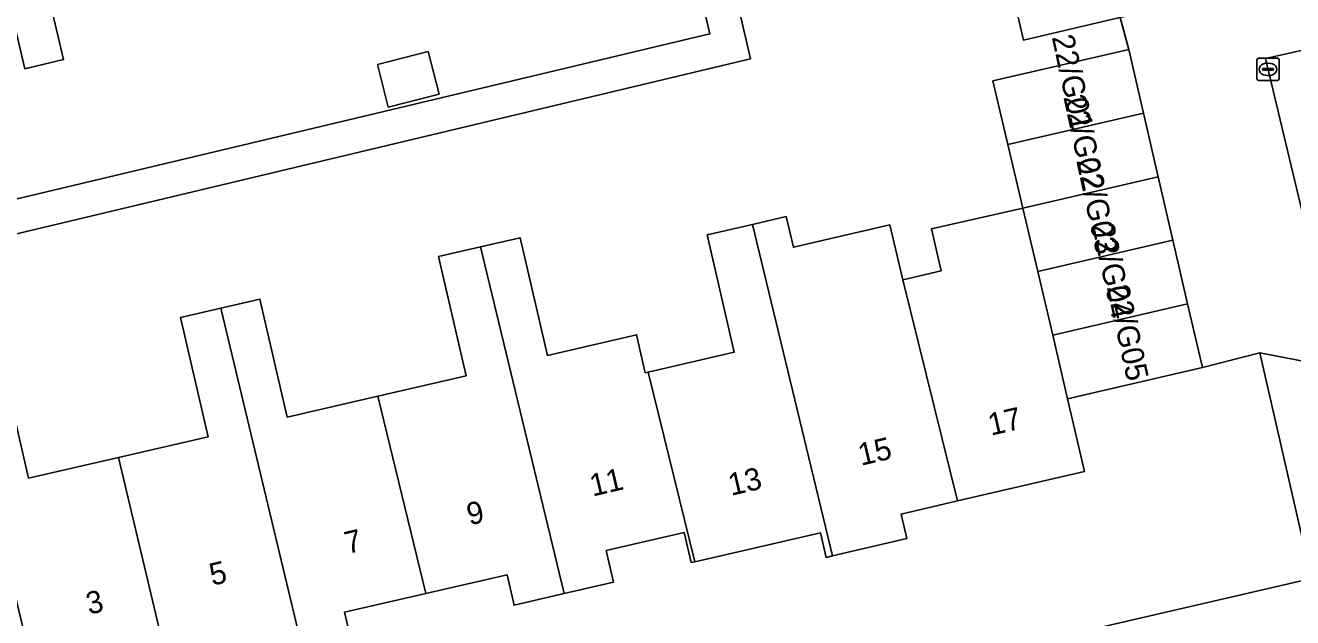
# Model space of a CAD drawing. Extents: x 158031 to 159244, y 380104 to 381214.
# Drawn here: x 158624 to 158681, y 380797.4 to 380824 of the extents above; entities that cross this region are included whole.
import ezdxf

# ---------------------------------------------------------------- set-up
doc = ezdxf.new("R2010")
doc.units = 0
for name, color, linetype in [('IMGEO_Erf', 7, 'Continuous'), ('IMGEO_Kolk', 7, 'Continuous'), ('IMGEO_Pand', 7, 'Continuous'), ('IMGEO_Pand_nummerreeks', 7, 'Continuous'), ('IMGEO_Rijbaan_lokaal_open', 7, 'Continuous'), ('IMGEO_Voetpad_open', 7, 'Continuous')]:
    doc.layers.add(name, color=color, linetype=linetype)

msp = doc.modelspace()

# ---------------------------------------------------------------- linework, layer by layer
at = {"layer": 'IMGEO_Erf'}
for points in [[(158619.439, 380815.23), (158654.76, 380823.659), (158652.218, 380834.399), (158647.944, 380833.388), (158649.195, 380828.097), (158647.343, 380827.659), (158645.589, 380827.244), (158644.337, 380832.534), (158640.266, 380831.571), (158636.181, 380830.604), (158637.434, 380825.306), (158635.642, 380824.882), (158633.881, 380824.465), (158632.636, 380829.729), (158628.571, 380828.767), (158624.437, 380827.789), (158625.69, 380822.495), (158623.945, 380822.082)], [(158672.677, 380824.263), (158668.856, 380823.374), (158667.866, 380827.629)], [(158655.594, 380826.799), (158656.575, 380822.533), (158619.79, 380813.755)], [(158623.374, 380806.866), (158624.117, 380803.653), (158628.154, 380804.587), (158632.194, 380805.522), (158630.951, 380810.889), (158632.757, 380811.307), (158634.516, 380811.714), (158635.746, 380806.4), (158639.827, 380807.345), (158643.791, 380808.262), (158642.55, 380813.627), (158644.438, 380814.064), (158646.221, 380814.477), (158647.446, 380809.184), (158651.456, 380810.113), (158651.852, 380808.4), (158651.976, 380808.429), (158655.853, 380809.326), (158654.632, 380814.602), (158656.664, 380815.072), (158658.189, 380815.425), (158658.508, 380814.046), (158662.847, 380815.05), (158663.432, 380812.582), (158665.154, 380812.981), (158664.714, 380814.879), (158668.834, 380815.814), (158668.157, 380818.673), (158667.48, 380821.533), (158673.591, 380822.947), (158673.21, 380824.387)], [(158649.671, 380791.7), (158681.807, 380799.138), (158679.48, 380809.301), (158676.904, 380808.635), (158670.839, 380807.231), (158671.598, 380803.951), (158665.887, 380802.629), (158663.356, 380802.043), (158663.614, 380800.934), (158660.269, 380800.159), (158659.981, 380800.092), (158659.723, 380801.202), (158654.075, 380799.895), (158653.912, 380799.857), (158653.6, 380801.204), (158650.096, 380800.393), (158650.424, 380798.976), (158648.201, 380798.461), (158645.948, 380797.94), (158645.632, 380799.309), (158641.979, 380798.463), (158638.327, 380797.618), (158638.653, 380796.208)]]:
    msp.add_lwpolyline(points, dxfattribs=at)
msp.add_lwpolyline([(158642.088, 380822.856), (158642.577, 380820.94), (158640.293, 380820.357), (158639.804, 380822.273)], close=True, dxfattribs=at)
at = {"layer": 'IMGEO_Kolk'}
for p, q in [((158679.352, 380821.63), (158679.352, 380822.482)), ((158679.427, 380822.556), (158680.279, 380822.556)), ((158680.353, 380822.482), (158680.353, 380821.63)), ((158679.611, 380822.05), (158679.611, 380822.062)), ((158680.049, 380822.013), (158679.651, 380822.013)), ((158679.654, 380822.099), (158680.052, 380822.099)), ((158679.84, 380822.336), (158679.865, 380822.336)), ((158680.095, 380822.062), (158680.095, 380822.05)), ((158680.279, 380821.556), (158679.427, 380821.556)), ((158679.863, 380821.776), (158679.838, 380821.776))]:
    msp.add_line(p, q, dxfattribs=at)
for points in [[(158679.352, 380821.63), (158679.352, 380822.482)], [(158679.427, 380822.556), (158680.279, 380822.556)], [(158680.353, 380822.482), (158680.353, 380821.63)], [(158680.279, 380821.556), (158679.427, 380821.556)]]:
    msp.add_lwpolyline(points, dxfattribs=at)
for centre, radius, start, end in [((158679.429, 380822.48), 0.0765, 91.552, 178.448), ((158679.429, 380822.48), 0.0765, 91.552, 178.448), ((158680.277, 380822.48), 0.0765, 1.552, 88.448), ((158680.277, 380822.48), 0.0765, 1.552, 88.448), ((158679.651, 380822.059), 0.0403, 85.8775, 175.7526), ((158679.648, 380822.049), 0.0366, 178.938, 274.7102), ((158680.052, 380822.056), 0.043, 264.8664, 352.4533), ((158680.056, 380822.061), 0.0386, 1.7309, 96.639), ((158679.429, 380821.632), 0.0765, 181.552, 268.448), ((158679.429, 380821.632), 0.0765, 181.552, 268.448), ((158680.277, 380821.632), 0.0765, 271.552, 358.448), ((158680.277, 380821.632), 0.0765, 271.552, 358.448)]:
    msp.add_arc(centre, radius, start, end, dxfattribs=at)
for centre, major_axis, ratio, start_param, end_param in [((158679.839, 380822.056), (-0.387, 0.002), 0.722429, 4.712389, 7.853982), ((158679.864, 380822.056), (-0.39, 0.002), 0.717154, 1.570796, 4.712389)]:
    msp.add_ellipse(centre, major_axis=major_axis, ratio=ratio, start_param=start_param, end_param=end_param, dxfattribs=at)
at = {"layer": 'IMGEO_Pand'}
for points in [[(158623.945, 380822.082), (158625.69, 380822.495), (158624.437, 380827.789), (158628.571, 380828.767), (158626.506, 380837.484), (158620.666, 380836.102)], [(158662.106, 380828.273), (158662.544, 380826.391), (158667.866, 380827.629), (158668.856, 380823.374), (158672.677, 380824.263), (158673.21, 380824.387), (158677.546, 380825.396), (158676.138, 380831.449)], [(158642.088, 380822.856), (158639.804, 380822.273), (158640.293, 380820.357), (158642.577, 380820.94)], [(158668.157, 380818.673), (158674.254, 380820.085), (158673.591, 380822.947), (158667.48, 380821.533)], [(158674.916, 380817.222), (158674.254, 380820.085), (158668.157, 380818.673), (158668.834, 380815.814)], [(158669.505, 380812.954), (158675.579, 380814.36), (158674.916, 380817.222), (158668.834, 380815.814)], [(158669.505, 380812.954), (158668.834, 380815.814), (158664.714, 380814.879), (158665.154, 380812.981), (158663.432, 380812.582), (158665.887, 380802.629), (158671.598, 380803.951), (158670.839, 380807.231), (158670.176, 380810.093)], [(158660.269, 380800.159), (158656.664, 380815.072), (158654.632, 380814.602), (158655.853, 380809.326), (158651.976, 380808.429), (158654.075, 380799.895), (158659.723, 380801.202), (158659.981, 380800.092)], [(158660.269, 380800.159), (158663.614, 380800.934), (158663.356, 380802.043), (158665.887, 380802.629), (158663.432, 380812.582), (158662.847, 380815.05), (158658.508, 380814.046), (158658.189, 380815.425), (158656.664, 380815.072)], [(158648.201, 380798.461), (158650.424, 380798.976), (158650.096, 380800.393), (158653.6, 380801.204), (158653.912, 380799.857), (158654.075, 380799.895), (158651.976, 380808.429), (158651.852, 380808.4), (158651.456, 380810.113), (158647.446, 380809.184), (158646.221, 380814.477), (158644.438, 380814.064)], [(158648.201, 380798.461), (158644.438, 380814.064), (158642.55, 380813.627), (158643.791, 380808.262), (158639.827, 380807.345), (158641.979, 380798.463), (158645.632, 380799.309), (158645.948, 380797.94)], [(158669.505, 380812.954), (158670.176, 380810.093), (158676.241, 380811.497), (158675.579, 380814.36)], [(158639.827, 380807.345), (158635.746, 380806.4), (158634.516, 380811.714), (158632.757, 380811.307), (158636.499, 380795.71), (158638.653, 380796.208), (158638.327, 380797.618), (158641.979, 380798.463)], [(158628.154, 380804.587), (158630.279, 380795.697), (158633.9, 380796.535), (158634.214, 380795.181), (158636.499, 380795.71), (158632.757, 380811.307), (158630.951, 380810.889), (158632.194, 380805.522)], [(158670.176, 380810.093), (158670.839, 380807.231), (158676.904, 380808.635), (158676.241, 380811.497)], [(158628.154, 380804.587), (158624.117, 380803.653), (158623.374, 380806.866), (158619.725, 380806.022), (158620.165, 380804.12), (158622.011, 380804.547), (158624.83, 380792.91), (158627.002, 380793.413), (158626.667, 380794.861), (158630.279, 380795.697)]]:
    msp.add_lwpolyline(points, close=True, dxfattribs=at)
at = {"layer": 'IMGEO_Rijbaan_lokaal_open'}
msp.add_lwpolyline([(158694.977, 380856.819), (158694.506, 380858.735), (158693.674, 380862.117), (158693.184, 380864.068), (158690.982, 380863.5), (158663.759, 380857.034), (158634.489, 380850.082), (158629.142, 380848.822), (158603.468, 380842.85), (158604.621, 380837.745), (158632.417, 380844.154), (158677.296, 380854.712), (158677.726, 380852.891), (158684.625, 380823.643), (158679.739, 380822.539), (158683.037, 380808.743), (158686.584, 380809.65), (158689.75, 380828.266), (158701.345, 380831.114)], close=True, dxfattribs=at)
at = {"layer": 'IMGEO_Voetpad_open'}
for points in [[(158683.037, 380808.743), (158679.739, 380822.539), (158684.625, 380823.643), (158677.726, 380852.891), (158677.296, 380854.712), (158632.417, 380844.154), (158604.621, 380837.745)], [(158673.21, 380824.387), (158673.591, 380822.947), (158674.254, 380820.085), (158674.916, 380817.222), (158675.579, 380814.36), (158676.241, 380811.497), (158676.904, 380808.635), (158679.48, 380809.301), (158682.758, 380808.672)], [(158693.242, 380795.503), (158694.028, 380798.377), (158688.983, 380799.726), (158686.657, 380800.579), (158686.299, 380800.758), (158685.923, 380800.989), (158685.569, 380801.252), (158685.24, 380801.546), (158684.938, 380801.868), (158684.667, 380802.216), (158684.427, 380802.586), (158684.222, 380802.977), (158684.052, 380803.384), (158683.919, 380803.805), (158683.825, 380804.236), (158682.758, 380808.672), (158679.48, 380809.301), (158681.807, 380799.138), (158649.671, 380791.7)]]:
    msp.add_lwpolyline(points, dxfattribs=at)
msp.add_lwpolyline([(158655.594, 380826.799), (158655.185, 380828.559), (158652.827, 380838.378), (158651.393, 380844.44), (158650.941, 380846.353), (158649.472, 380846.005), (158650.164, 380843.079), (158651.315, 380838.214), (158652.218, 380834.399), (158654.76, 380823.659), (158619.439, 380815.23), (158613.371, 380813.782), (158610.493, 380813.095), (158610.841, 380811.62), (158613.768, 380812.318), (158619.79, 380813.755), (158656.575, 380822.533)], close=True, dxfattribs=at)

# ---------------------------------------------------------------- texts
at = {"layer": 'IMGEO_Pand_nummerreeks'}
for s, rotation, p in [('22/G01', 282.1715, (158670.127, 380823.507)), ('22/G02', 282.1715, (158670.649, 380820.808)), ('22/G03', 282.1715, (158671.226, 380817.953)), ('22/G04', 282.1715, (158671.93, 380815.04)), ('22/G05', 282.1715, (158672.603, 380812.255)), ('17', 13.0326, (158667.393, 380805.564)), ('15', 13.0326, (158661.552, 380804.212)), ('11', 13.209, (158649.484, 380802.826)), ('13', 13.0326, (158655.711, 380802.86)), ('9', 13.209, (158643.95, 380801.527)), ('7', 13.209, (158638.457, 380800.237)), ('5', 13.209, (158632.38, 380798.811)), ('3', 13.209, (158626.832, 380797.508))]:
    msp.add_text(s, height=1, rotation=rotation, dxfattribs=at).set_placement(p)

doc.saveas('drawing.dxf')
